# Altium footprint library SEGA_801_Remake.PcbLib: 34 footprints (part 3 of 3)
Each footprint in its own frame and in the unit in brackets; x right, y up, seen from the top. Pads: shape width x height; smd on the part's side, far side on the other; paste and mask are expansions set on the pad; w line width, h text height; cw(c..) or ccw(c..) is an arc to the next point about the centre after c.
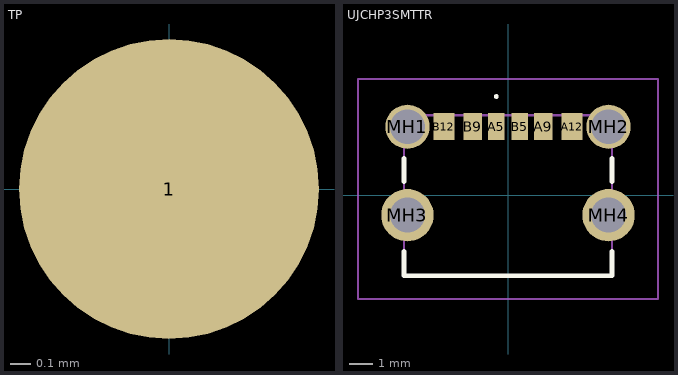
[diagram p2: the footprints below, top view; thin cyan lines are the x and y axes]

## TP [mm] "Test point"
pads (1):
  round 1.5 smd: 1(0,0)

## UJCHP3SMTTR [mm]
pads (10):
  rect 0.7x1.15 smd: A5(-0.5,2.955) B5(0.5,2.955)
  rect 0.8x1.15 smd: A9(1.52,2.955) B9(-1.52,2.955)
  rect 0.9x1.15 smd: A12(2.75,2.955) B12(-2.75,2.955)
  round 1.9 hole 1.5: MH1(-4.32,2.95) MH2(4.32,2.95)
  round 2.25 hole 1.5: MH3(-4.32,-0.85) MH4(4.32,-0.85)
Top Overlay:
  lines w0.1: -0.5,4.2 ccw(c-0.5,4.25) -0.5,4.3 ccw(c-0.5,4.25) -0.5,4.2
  lines w0.2: -4.47,-2.4 -4.47,-3.45 4.47,-3.45 4.47,-2.4 ; -4.47,0.6 -4.47,1.6 ; 4.47,0.6 4.47,1.6
Mechanical 13:
  lines w0.1: -4.47,-3.45 4.47,-3.45 4.47,3.45 -4.47,3.45 -4.47,-3.45
Mechanical 15:
  lines w0.1: -6.445,-4.45 6.445,-4.45 6.445,5 -6.445,5 -6.445,-4.45
3D body "UJC-HP-3-SMT-TR.stp": height 3.46, standoff -5, extent -4.965,-3.45 4.97,3.599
